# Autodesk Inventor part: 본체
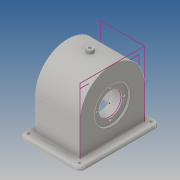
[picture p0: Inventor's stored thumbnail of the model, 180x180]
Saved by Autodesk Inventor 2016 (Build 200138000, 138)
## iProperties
Created: 2016-01
Part Number: 본체
Material: Generic
Document SubType Name: Modeling
Designer: Administrator
Density: 1 g/cm^3
Appearance: Default
Author: Administrator
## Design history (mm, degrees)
sketch "스케치1"
  geometry: L1 (52, 70)-(-52, 70); L2 (-52, 70)-(-52, -70); L3 (-52, -70)-(52, -70); L4 (52, -70)-(52, 70); L5 (0, 0)-(0, -25.231); L6 (0, 0)-(18.742, 0)
  constraints: 12 end point, 2 horizontal, 2 parallel, 1 perpendicular, 1 vertical
  dimensions: "d0" = 140 distance of L3.end L1.start; "d1" = 104 distance of L2.end L3.end; "d2" = 52 horizontal distance of L3.end L5.end; "d3" = 70 vertical distance of L6.end L3.end
sketch "스케치2"
  geometry: 1 further point
extrude "돌출1" new body sketch "스케치1" distance "d4" = 7; taper "d5" = 0 deg
sketch "스케치3"
  geometry: L1 (-52, -70)-(52, -70) reference; L2 (0, 0)-(-107.012, 0); L3 (0, 0)-(0, -120.436); L4 (-44, -70)-(-44, -62); L5 (-44, -62)-(0, -62); C1 r 2.5 at (-44, -62); C2 r 2.5 at (-44, 62); C3 r 2.5 at (44, -62); C4 r 2.5 at (44, 62)
  constraints: 8 end point, 4 centre point, 2 horizontal, 2 perpendicular, 2 point on line, 2 vertical, 1 coincident, 6 other
  dimensions: "d7" = 44 distance of L4.end L5.end; "d8" = 8 distance of L4.start L4.end; "d9" = 5 diameter of C1; "d12" = 124 distance of C1.centre C2.centre; "d15" = 88 distance of C1.centre C3.centre
extrude "돌출2" cut sketch "스케치3" distance "d18" = 7; taper "d19" = 0 deg
fillet "모깎기1" dims "d20" = 8
fillet "모깎기2" dims "d21" = 3
sketch "스케치4"
  geometry: L1 (0, 0)-(0, -57.891); L2 (0, 0)-(-46.5, 0); L3 (-38.5, -56)-(38.5, -56); L4 (38.5, -56)-(38.5, 56); L5 (38.5, 56)-(-38.5, 56); L6 (-38.5, 56)-(-38.5, -56)
  constraints: 12 end point, 2 horizontal, 2 parallel, 1 perpendicular, 1 vertical
  dimensions: "d22" = 112 distance of L5.end L3.start; "d23" = 38.5 horizontal distance of L1.end L3.start; "d24" = 77 distance of L3.start L3.end; "d25" = 56 vertical distance of L3.start L2.end
extrude "돌출3" join sketch "스케치4" distance "d26" = 114; taper "d27" = 0 deg
sketch "스케치5"
  geometry: L1 (112, 0)-(0, 0) reference; L2 (112, 0)-(112, 114) reference; L3 (0, 114)-(112, 114) reference; L4 (0, 0)-(0, 114) reference; L5 (56, 3.935)-(56, 101.341); L6 (0, 67.63)-(0, 114); L7 (112, 114)-(112, 67.63); A1 r 57 centre (56, 57) between (0, 67.63) and (112, 67.63); 1 further point
  constraints: 6 end point, 3 point on line, 2 point on circle, 1 centre point, 1 collinear, 1 vertical
  dimensions: "d28" = 114 diameter of A1
extrude "돌출4" cut sketch "스케치5" distance "d29" = 114; taper "d30" = 0 deg
sketch "스케치6"
  geometry: C1 r 20 at (56, 53); A1 r 57 centre (56, 57) between (112, 67.63) and (0, 67.63) reference; 1 further point
  constraints: 1 centre point
  dimensions: "d31" = 4 distance of C1.centre A1.centre; "d32" = 40 diameter of C1
sketch "스케치7"
  geometry: L1 (0, 0)-(112, 0); L2 (112, 0)-(112, 114); L3 (112, 114)-(0, 114); L4 (0, 114)-(0, 0); 1 further point
  constraints: 8 end point, 2 parallel, 1 horizontal, 1 perpendicular
extrude "돌출5" join sketch "스케치7" distance "d33" = 77; taper "d34" = 0 deg
sketch "스케치8"
  geometry: L1 (112, 114)-(0, 114) reference; L2 (0, 0)-(0, 114) reference; L3 (112, 0)-(0, 0) reference; L4 (112, 0)-(112, 114) reference; 1 further point
extrude "돌출6" cut sketch "스케치6" distance "d35" = 77; taper "d36" = 0 deg
sketch "스케치9"
  geometry: C1 r 20 at (56, 53) reference; C2 r 31 at (56, 53); 1 further point
  constraints: 1 centre point, 1 coincident
  dimensions: "d37" = 62 diameter of C2
extrude "돌출7" join sketch "스케치9" distance "d38" = 10; taper "d39" = 0 deg
sketch "스케치10"
  geometry: L1 (0, 24)-(0, -24); L2 (24, 0)-(-24, 0); C1 r 31 at (0, 0) reference; A1 r 24 centre (0, 0) between (0, 24) and (0, -24); 1 further point
  constraints: 4 end point, 4 point on circle, 1 centre point, 1 coincident, 1 perpendicular, 1 vertical
  dimensions: "d40" = 48 diameter of A1
hole "구멍1" sketch "스케치10" at (0, 24), (-24, 0), (0, -24), (24, 0) diameter "d41" = 3; stored, may be unused: countersink angle "d45" = 82 deg, drill point angle "d47" = 118 deg; dims "d42" = 19.05, "d43" = 9.525, "d44" = 6.35, "d46" = 6
sketch "스케치11"
  geometry: L1 (44, -70)-(-44, -70) reference; L2 (-44, 70)-(44, 70) reference; L3 (-52, -62)-(-52, 62) reference; L4 (52, 62)-(52, -62) reference; L5 (52, 0)-(-52, 0); L6 (0, -70)-(0, 70); L7 (33.5, 51)-(-33.5, 51); L8 (-33.5, 51)-(-33.5, -51); L9 (-33.5, -51)-(33.5, -51); L10 (33.5, -51)-(33.5, 51); 1 further point
  constraints: 12 end point, 5 midpoint, 2 parallel, 1 horizontal, 1 perpendicular
  dimensions: "d48" = 51 vertical distance of L9.end L5.start; "d49" = 102 distance of L9.end L7.start; "d50" = 33.5 horizontal distance of L7.start L6.end; "d51" = 67 distance of L7.start L7.end
extrude "돌출8" cut sketch "스케치11" distance "d52" = 108; taper "d53" = 0 deg
sketch "스케치12"
  geometry: C1 r 6 at (-38.5, 56); 1 further point
  constraints: 1 centre point, 1 coincident
  dimensions: "d54" = 12 diameter of C1
extrude "돌출9" join sketch "스케치12" distance "d55" = 6; taper "d56" = 0 deg
sketch "스케치13"
  geometry: C1 r 6 at (0, 0) reference; C2 r 2.5 at (0, 0)
  constraints: 1 centre point, 1 coincident
  dimensions: "d57" = 5 diameter of C2
hole "구멍2" sketch "스케치13" at (0, 0) diameter "d58" = 5; stored, may be unused: countersink angle "d62" = 82 deg, drill point angle "d64" = 118 deg; dims "d59" = 19.05, "d60" = 9.525, "d61" = 6.35, "d63" = 6
sketch "스케치14"
  geometry: C1 r 20 at (51, 60) reference; C2 r 28 at (51, 60); 1 further point
  constraints: 1 centre point, 1 coincident
  dimensions: "d65" = 56 diameter of C2
node "3D 스케치1"
node "3D 스케치2"
sketch "스케치15"
  geometry: L1 (102, 0)-(0, 0) reference; L2 (102, 0)-(102, 108) reference; L3 (102, 108)-(0, 108) reference; L4 (0, 0)-(0, 108) reference; C1 r 20 at (51, 60) reference; 1 further point
extrude "돌출10" join sketch "스케치14" distance "d66" = 16; taper "d67" = 0 deg
feature "면 기울기1" dims angle "d68" = 50 deg
sketch "스케치16"
  geometry: C1 r 20 at (56, 53) reference; C2 r 31 at (56, 53); 1 further point
  constraints: 1 centre point, 1 coincident
  dimensions: "d69" = 62 diameter of C2
extrude "돌출11" cut sketch "스케치16" distance "d70" = 3; taper "d71" = 0 deg
fillet "모깎기3" dims "d72" = 1
sketch "스케치17"
  geometry: L1 (77, -113)-(0, -113) reference; L2 (77, -113)-(77, 0) reference; L3 (0, 0)-(77, 0) reference; L4 (0, -113)-(0, 0) reference; 1 further point
sketch "스케치18"
  geometry: L1 (24, 0)-(-24, 0); L2 (0, 24)-(0, -24); C1 r 1.5 at (24, 0) reference; C2 r 1.5 at (-24, 0) reference; C3 r 1.5 at (0, 24) reference; C4 r 1.5 at (0, -24) reference; 1 further point
  constraints: 4 end point, 1 horizontal, 1 vertical
hole "구멍3" sketch "스케치18" at (0, 24), (-24, 0), (0, -24), (24, 0) diameter "d73" = 3; stored, may be unused: countersink angle "d77" = 82 deg, drill point angle "d79" = 118 deg; dims "d74" = 19.05, "d75" = 3.0226, "d76" = 6.35, "d78" = 9
fillet "모깎기4" dims "d80" = 51
fillet "모깎기5" dims "d81" = 56
fillet "모깎기6" dims "d82" = 9
fillet "모깎기7" dims "d83" = 14
fillet "모깎기8" dims "d84" = 14
sketch "스케치19"
  geometry: L1 (11.698, 29.525)-(64.271, 29.525); L2 (64.271, 29.525)-(64.271, 5.816); L3 (64.271, 5.816)-(11.698, 5.816); L4 (11.698, 5.816)-(11.698, 29.525); 1 further point
  constraints: 2 other
feature "엠보싱1" sketch "스케치19" dims "d7" = 44, "d8" = 8, "d9" = 5, "d12" = 124, "d15" = 88, "d85" = 0.5, "d86" = 0
fillet "모깎기9" dims "d87" = 14
node "솔리드1"
